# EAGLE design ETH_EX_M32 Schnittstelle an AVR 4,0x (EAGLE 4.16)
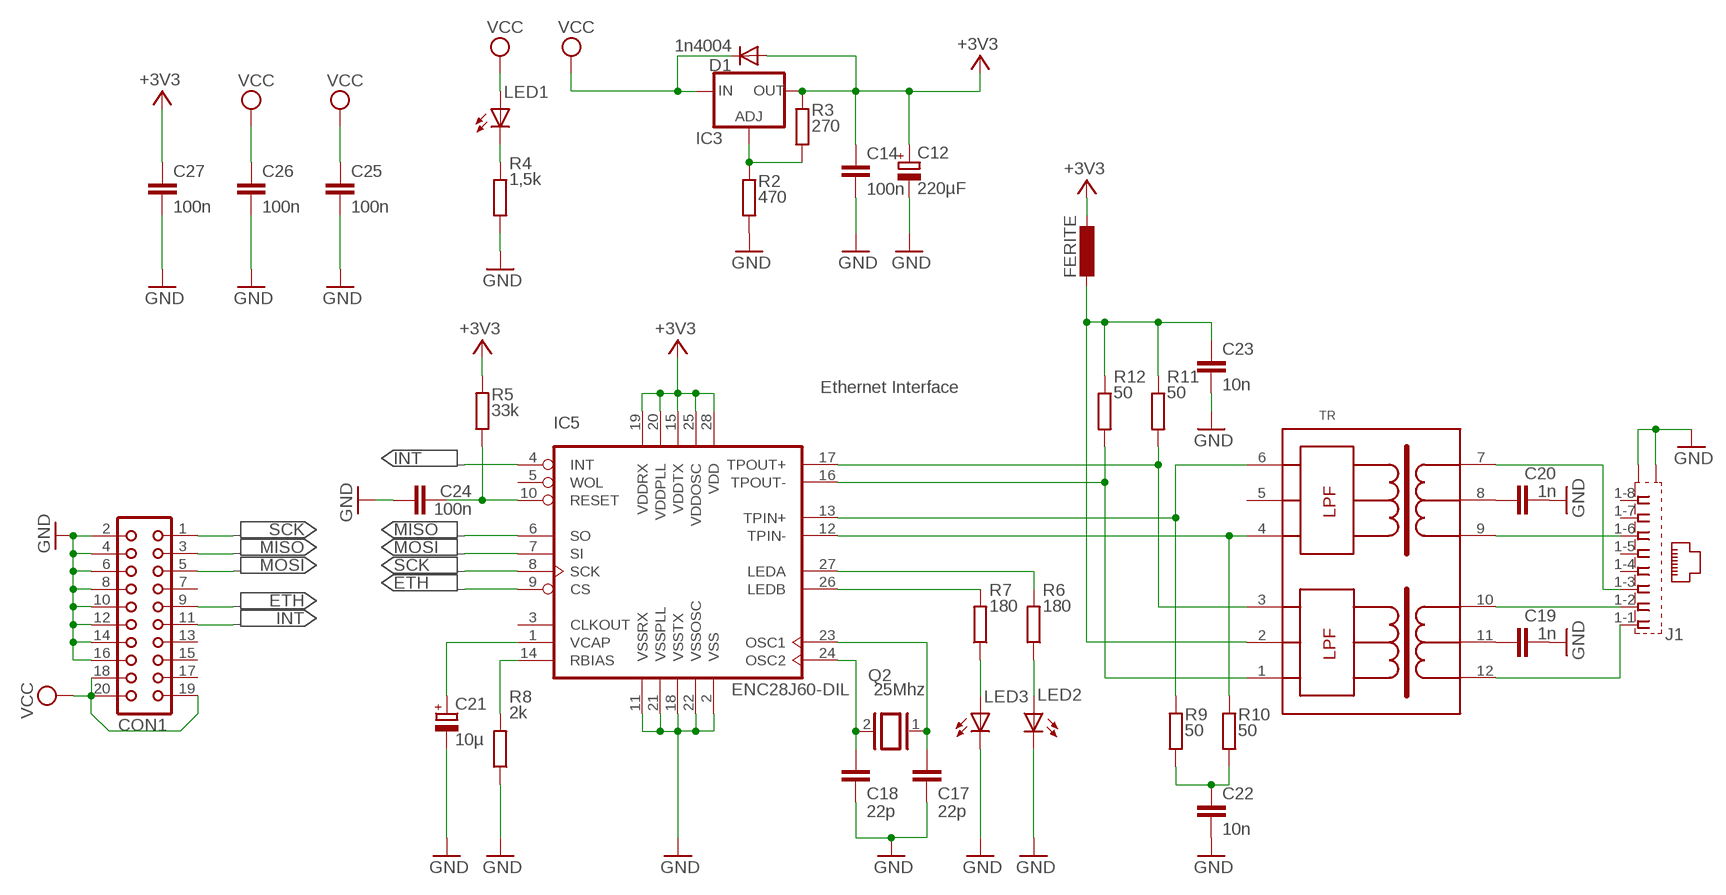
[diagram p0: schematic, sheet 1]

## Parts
C12  220µF  CPOL-EUE3.5-8  [E3,5-8]
C14  100n  C-EU025-024X044  [C025-024X044]
C17  22p  C-EU025-024X044  [C025-024X044]
C18  22p  C-EU025-024X044  [C025-024X044]
C19  1n  C-EU025-024X044  [C025-024X044]
C20  1n  C-EU025-024X044  [C025-024X044]
C21  10µ  CPOL-EUE2.5-5  [E2,5-5]
C22  10n  C-EU025-025X050  [C025-025X050]
C23  10n  C-EU025-025X050  [C025-025X050]
C24  100n  C-EU025-024X044  [C025-024X044]
C25  100n  C-EU025-025X050  [C025-025X050]
C26  100n  C-EU025-025X050  [C025-025X050]
C27  100n  C-EU025-025X050  [C025-025X050]
CON1  CON20  [CON20]
D1  1n4004  DIODE-D-7.5  [D-7.5]
FERITE  L-EU0204/5  [0204/5]
IC3  LM317TS  [317TS]
IC5  ENC28J60-DIL  [DIL28-3]
J1  557786-1  [557786-1]
LED1  LED3MM  [LED3MM]
LED2  LED3MM  [LED3MM]
LED3  LED3MM  [LED3MM]
Q2  25Mhz  XTAL/S  [QS]
R2  470  R-EU_0204/7  [0204/7]
R3  270  R-EU_0204/7  [0204/7]
R4  1,5k  R-EU_0204/7  [0204/7]
R5  33k  R-EU_0204/7  [0204/7]
R6  180  R-EU_0204/7  [0204/7]
R7  180  R-EU_0204/7  [0204/7]
R8  2k  R-EU_0204/7  [0204/7]
R9  50  R-EU_0204/7  [0204/7]
R10  50  R-EU_0204/7  [0204/7]
R11  50  R-EU_0204/7  [0204/7]
R12  50  R-EU_0204/7  [0204/7]
TR  20F001  [DIL16/12]

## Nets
+3V3: C12.+ C14.1 C27.1 D1.A FERITE.1 IC3.2(OUT) IC5.15(VDDTX) IC5.19(VDDRX) IC5.20(VDDPLL) IC5.25(VDDOSC) IC5.28(VDD) R3.2 R5.2
ETH: CON1.9 IC5.9(CS)
GND: C12.- C14.2 C17.1 C18.1 C19.2 C20.2 C21.- C22.2 C23.2 C24.1 C25.1 C26.2 C27.2 CON1.2 CON1.4 CON1.6 CON1.8 CON1.10 CON1.12 CON1.14 CON1.16 IC5.2(VSS) IC5.11(VSSRX) IC5.18(VSSTX) IC5.21(VSSPLL) IC5.22(VSSOSC) J1.G1(S2) J1.G2(S1) LED2.K(C) LED3.K(C) R2.1 R4.1 R8.1
INT: CON1.11 IC5.4(INT)
MISO: CON1.3 IC5.6(SO)
MOSI: CON1.5 IC5.7(SI)
N$4: LED1.K(C) R4.2
N$7: J1.1-1 TR.12
N$8: J1.1-2 TR.10
N$11: IC5.27(LEDA) R6.2
N$12: IC3.1(ADJ) R2.2 R3.1
N$13: J1.1-6 TR.9
N$14: IC5.26(LEDB) R7.2
N$15: J1.1-3 TR.7
N$16: C20.1 TR.8
N$17: C19.1 TR.11
N$18: LED3.A R7.1
N$19: LED2.A R6.1
N$20: C18.2 IC5.24(OSC2) Q2.2
N$21: C17.2 IC5.23(OSC1) Q2.1
N$22: IC5.12(TPIN-) R10.2 TR.4
N$23: IC5.13(TPIN+) R9.2 TR.6
N$24: IC5.16(TPOUT-) R12.2 TR.1
N$25: IC5.17(TPOUT+) R11.2 TR.3
N$26: IC5.14(RBIAS) R8.2
N$27: C21.+ IC5.1(VCAP)
N$29: C22.1 R9.1 R10.1
N$30: C24.2 IC5.10(RESET) R5.1
N$248: C23.1 FERITE.2 R11.1 R12.1 TR.2
SCK: CON1.1 IC5.8(SCK)
VCC: C25.2 C26.1 CON1.18 CON1.19 CON1.20 D1.C IC3.3(IN) LED1.A
Unconnected: CON1.7 CON1.13 CON1.15 CON1.17 IC5.3(CLKOUT) IC5.5(WOL) J1.1-4 J1.1-5 J1.1-7 J1.1-8 TR.5

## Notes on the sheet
- Ethernet Interface

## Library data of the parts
C12 C21 = rcl:CPOL-EU: POLARIZED CAPACITOR, European symbol
C14 C17-C20 C22-C27 = rcl:C-EU: CAPACITOR, European symbol
CON1 = con-harting:CON20: CONNECTOR
D1 = diode:DIODE-: DIODE
FERITE = rcl:L-EU: INDUCTOR, European symbol
IC3 = v-reg:LM317TS: VOLTAGE REGULATOR
IC5 = enc28j60centered:ENC28J60-*: Microchip 10Mbit Ethernet controller with SPI interface Improved SOIC28 layout (pads in 0.01 raster, pin1 slightly smaller). Pin 6 (SO) changed from Out (paralleling several Outs gives an error) to OC. Author: Profi from mikrocontroller.net - forum Date: 2006.0827
J1 = con-amp:557786-1: AMP connector
LED1-LED3 = led:LED: LED
Q2 = special:XTAL/S: CRYSTAL
R2-R12 = rcl:R-EU_: RESISTOR, European symbol
TR = Realtek:20F001

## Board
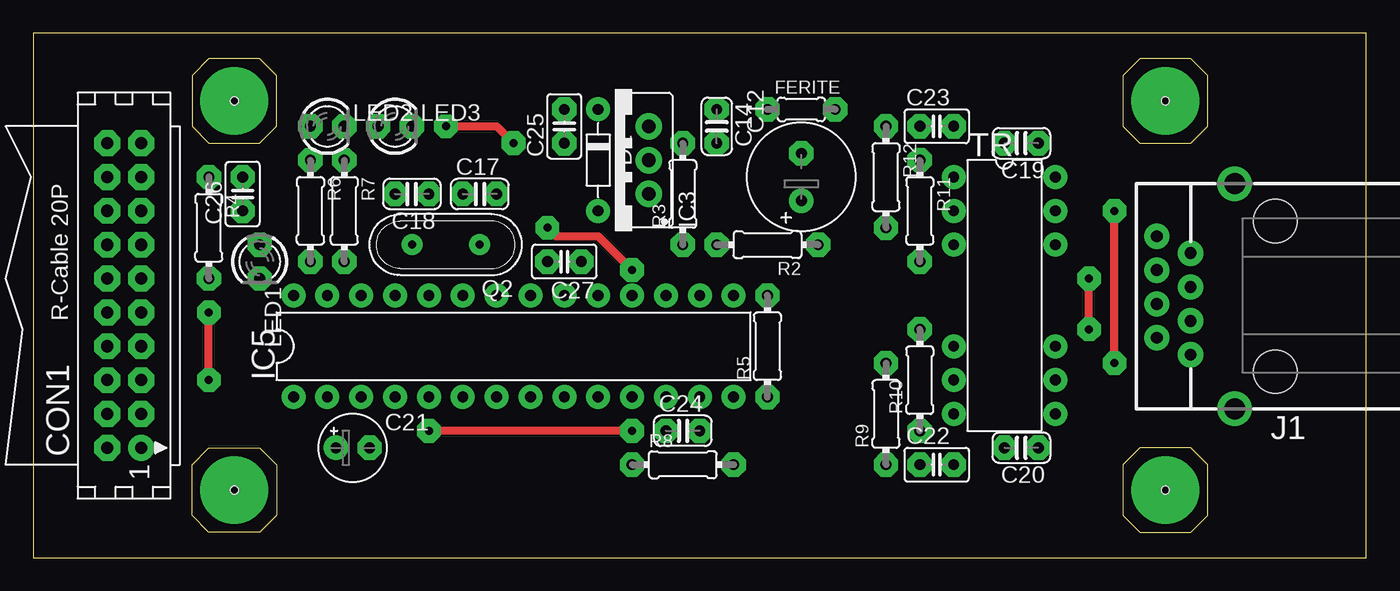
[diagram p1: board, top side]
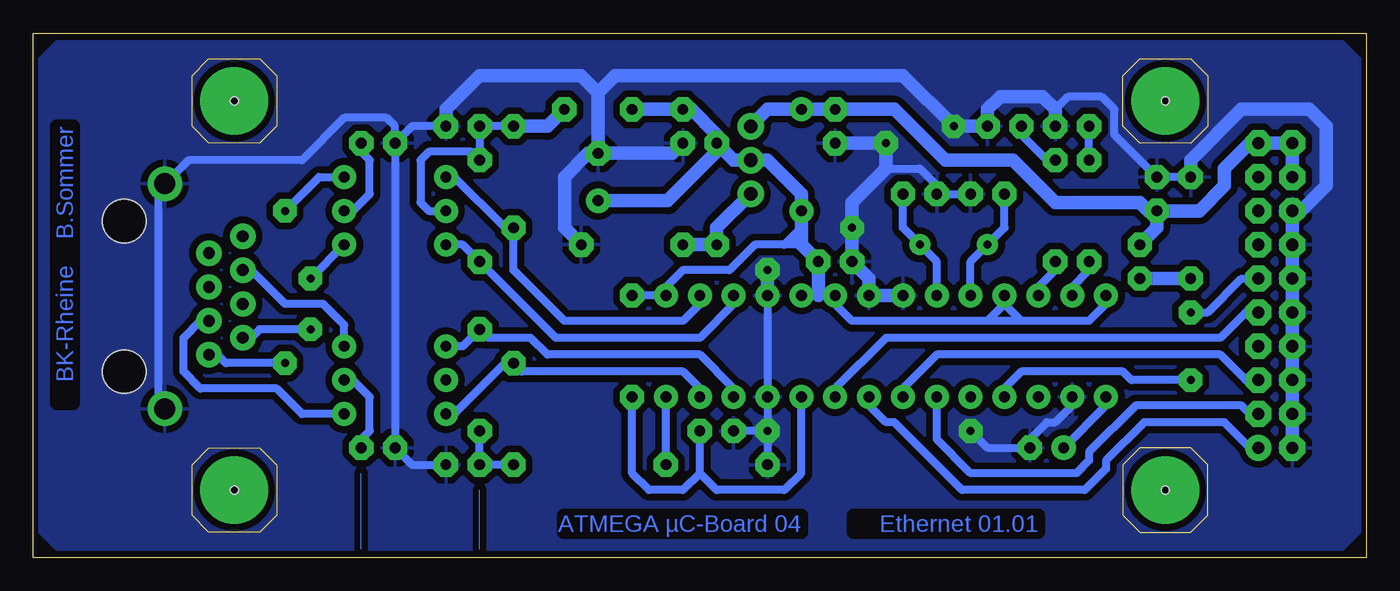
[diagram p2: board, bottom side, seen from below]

Size 100 x 39.36 mm. Coordinates in mm from the lower left corner, seen from the top.
Outline: 0,0 100,0 100,39.36 0,39.36 0,0
Outline: 16.98,37.46 13.17,37.46 11.9,36.19 11.9,32.38 13.17,31.11 16.98,31.11 18.25,32.38 18.25,36.19 16.98,37.46
Outline: 13.17,8.25 16.98,8.25 18.25,6.98 18.25,3.17 16.98,1.9 13.17,1.9 11.9,3.17 11.9,6.98 13.17,8.25
Outline: 83.02,1.9 86.83,1.9 88.1,3.17 88.1,6.98 86.83,8.25 83.02,8.25 81.75,6.98 81.75,3.17 83.02,1.9
Outline: 83.02,31.11 86.83,31.11 88.1,32.38 88.1,36.19 86.83,37.46 83.02,37.46 81.75,36.19 81.75,32.38 83.02,31.11
Copper layers (1*16): Top 0.035mm / dielectric 1.5mm / Bottom 0.035mm
Design rules "sommer_01": minimum track width 24mil, minimum drill 0.5mm, track to track 20mil, track to pad 24mil, pad to pad 24mil, via to via 24mil, smd to smd 8mil, copper to edge 0mil, drill to drill 8mil, minimum pad ring 20mil, minimum via ring 20mil, stop-mask expansion 4mil, vias tented up to drill 0mil, thermal gap 20mil
Holes 0.6 mm at 15.08,5.08 15.08,34.29 84.92,34.29 84.92,5.08

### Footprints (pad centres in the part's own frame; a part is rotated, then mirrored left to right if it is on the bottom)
E3,5-8 = drill 0.813 pad 1.6 round: + -1.778,0 | drill 0.813 pad 1.6 octagon: - 1.778,0
C025-024X044 = drill 0.813 octagon: 1 -1.27,0; 2 1.27,0
E2,5-5 = drill 0.813 pad 1.6 round: + -1.27,0 | drill 0.813 pad 1.6 octagon: - 1.27,0
C025-025X050 = drill 0.813 octagon: 1 -1.27,0; 2 1.27,0
CON20 = drill 0.914 round: 1 -11.43,-1.27 | drill 0.914 octagon: 2 -11.43,1.27; 3 -8.89,-1.27; 4 -8.89,1.27; 5 -6.35,-1.27; 6 -6.35,1.27; 7 -3.81,-1.27; 8 -3.81,1.27; 9 -1.27,-1.27; 10 -1.27,1.27; 11 1.27,-1.27; 12 1.27,1.27; 13 3.81,-1.27; 14 3.81,1.27; 15 6.35,-1.27; 16 6.35,1.27; 17 8.89,-1.27; 18 8.89,1.27; 19 11.43,-1.27; 20 11.43,1.27
D-7.5 = drill 0.813 long: A 3.81,0; C -3.81,0
0204/5 = drill 0.813 octagon: 1 -2.54,0; 2 2.54,0
317TS = drill 1.016 long: 1 -2.54,-2.54; 2 0,-2.54; 3 2.54,-2.54
DIL28-3 = drill 0.813 long: 1 -16.51,-3.81; 2 -13.97,-3.81; 3 -11.43,-3.81; 4 -8.89,-3.81; 5 -6.35,-3.81; 6 -3.81,-3.81; 7 -1.27,-3.81; 8 1.27,-3.81; 9 3.81,-3.81; 10 6.35,-3.81; 11 8.89,-3.81; 12 11.43,-3.81; 13 13.97,-3.81; 14 16.51,-3.81; 15 16.51,3.81; 16 13.97,3.81; 17 11.43,3.81; 18 8.89,3.81; 19 6.35,3.81; 20 3.81,3.81; 21 1.27,3.81; 22 -1.27,3.81; 23 -3.81,3.81; 24 -6.35,3.81; 25 -8.89,3.81; 26 -11.43,3.81; 27 -13.97,3.81; 28 -16.51,3.81
557786-1 = drill 0.889 round: 1-1 -4.445,6.35; 1-2 -3.175,8.89; 1-3 -1.905,6.35; 1-4 -0.635,8.89; 1-5 0.635,6.35; 1-6 1.905,8.89; 1-7 3.175,6.35; 1-8 4.445,8.89 | drill 1.575 pad 2.184 round: G1 -8.509,3.048; G2 8.382,3.048 | hole 3.251: -5.715,0; 5.588,0
LED3MM = drill 0.813 octagon: A -1.27,0; K 1.27,0
QS = drill 0.61 long: 1 -2.54,0; 2 2.54,0
0204/7 = drill 0.813 octagon: 1 -3.81,0; 2 3.81,0
DIL16/12 = drill 0.813 long: 1 -8.89,-3.81; 2 -6.35,-3.81; 3 -3.81,-3.81; 4 3.81,-3.81; 5 6.35,-3.81; 6 8.89,-3.81; 7 8.89,3.81; 8 6.35,3.81; 9 3.81,3.81; 10 -3.81,3.81; 11 -6.35,3.81; 12 -8.89,3.81

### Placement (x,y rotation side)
C12  57.62,28.57 90 top
C14  51.27,32.38 270 top
C17  33.49,27.3 0 top
C18  28.41,27.3 180 top
C19  74.13,31.11 180 top
C20  74.13,8.25 180 top
C21  23.96,8.25 0 top
C22  67.78,6.98 0 top
C23  67.78,32.38 0 top
C24  48.73,9.52 0 top
C25  39.84,32.38 90 top
C26  15.71,27.3 90 top
C27  39.84,22.22 180 top
CON1  6.82,19.68 90 top
D1  42.38,29.84 270 top
FERITE  57.62,33.65 0 top
IC3  43.65,29.84 90 top
IC5  36.03,15.87 0 top
J1  93.18,19.68 90 top
LED1  16.98,22.22 270 top
LED2  22.06,32.38 0 top
LED3  27.14,32.38 0 top
Q2  30.95,23.49 180 top
R2  55.08,23.49 180 top
R3  48.73,27.3 90 top
R4  13.17,24.76 270 top
R5  55.08,15.87 90 top
R6  20.79,26.03 270 top
R7  23.33,26.03 270 top
R8  48.73,6.98 0 top
R9  63.97,10.79 90 top
R10  66.51,13.33 90 top
R11  66.51,26.03 270 top
R12  63.97,28.57 270 top
TR  72.86,19.68 270 top

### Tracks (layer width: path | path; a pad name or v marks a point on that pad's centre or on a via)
+3V3
  Bottom 0.61: R5.2 IC5.15 52.54,20.31 51.27,21.58 47.78,21.58 45.87,23.49 43.65,23.49 | IC5.19 41.11,19.68 IC5.20 39.84,19.04 38.57,17.77 28.41,17.77 | IC5.28 19.52,19.04 20.79,17.77 25.87,17.77 | 25.87,17.77 27.14,19.04 | 27.14,19.04 IC5.25 | 27.14,19.04 28.41,17.77 | 25.87,17.77 28.41,17.77 | 42.38,23.49 43.65,23.49 | 42.38,24.76 43.65,23.49
  Bottom 1.016: R3.2 47.46,29.84 IC3.2 44.92,29.84 42.38,27.3 D1.A 42.38,24.76 42.38,23.49 C27.1 41.11,19.68 | C12.+ 52.41,26.79 48.73,30.47 R3.2 | R3.2 48.73,31.74 50.63,33.65 C14.1 FERITE.1
ETH
  Bottom 0.61: CON1.9 9.04,18.41 10.95,16.5 36.03,16.5 39.84,12.7 IC5.9
GND  (via drill 0.6 pad 1.78)
  Top 0.61: v30.95,32.38 34.76,32.38 v36.03,31.11 | v38.57,24.76 39.2,24.12 42.38,24.12 v44.92,21.58 | v44.92,9.52 v29.68,9.52
  Bottom 0.61: J1.G1 90.13,11.55 90.64,12.06 90.64,27.3 90.13,27.81 J1.G2 88.35,29.84 79.84,29.84 76.67,33.02 73.5,33.02 72.86,32.38 C19.2 | IC5.18 IC5.11 v44.92,9.52 | v44.92,9.52 R8.1 | C23.2 71.59,32.38 C19.2 | C22.2 71.59,6.98 C20.2 C19.2 | C18.1 C17.1 32.22,27.93 33.49,29.2 36.03,29.2 | R4.1 C26.2 18.88,31.74 18.88,33.65 19.84,34.6 22.38,34.6 23.33,33.65 | v29.68,9.52 28.41,8.25 C21.- 25.23,8.89 23.96,10.16 23.33,10.16 22.06,11.43 IC5.2 | v44.92,9.52 C24.1
  Bottom 1.016: 57.62,34.92 C12.- | 57.62,34.92 58.89,36.19 66.51,36.19 69.05,33.65 C23.2 | CON1.2 CON1.4 CON1.6 CON1.8 CON1.10 CON1.12 CON1.14 CON1.16 4.92,26.03 3.01,27.93 3.01,32.38 4.28,33.65 9.36,33.65 13.17,29.84 R4.1 | 57.62,34.92 56.35,36.19 34.76,36.19 v30.95,32.38 LED3.K 28.41,33.65 27.46,34.6 24.28,34.6 23.33,33.65 LED2.K | C25.1 v36.03,31.11 36.03,29.2 38.57,26.66 v38.57,24.76 C27.2 37.3,20.95 IC5.21 IC5.22 | v44.92,21.58 IC5.18 | C12.- 52.03,30.35 C14.2 | C12.- 58.38,30.35 60.16,28.57 60.16,24.76 R2.1
  pour Bottom: 0.47,37.46 1.74,38.73 98.26,38.73 99.53,37.46 99.53,1.9 98.26,0.63 1.74,0.63 0.47,1.9
INT  (via drill 0.6 pad 1.78)
  Top 0.61: v13.17,13.33 v13.17,18.41
  Bottom 0.61: v13.17,18.41 11.9,18.41 9.36,20.95 CON1.11 | v13.17,13.33 17.61,13.33 18.25,13.97 25.87,13.97 27.14,12.7 IC5.4
MISO
  Bottom 0.61: CON1.3 8.73,10.79 9.36,11.43 17.3,11.43 20.79,7.93 20.79,7.3 21.74,6.34 29.68,6.34 32.22,8.89 IC5.6
MOSI
  Bottom 0.61: IC5.7 34.76,12.7 32.22,15.24 10.95,15.24 9.04,13.33 CON1.5
N$1  (via drill 0.6 pad 5.08)
  other vias: 15.08,34.29
N$2  (via drill 0.6 pad 5.08)
  other vias: 15.08,5.08
N$3  (via drill 0.6 pad 5.08)
  other vias: 84.92,5.08
N$4
  Bottom 1.016: R4.2 LED1.K
N$5  (via drill 0.6 pad 5.08)
  other vias: 84.92,34.29
N$6
  Bottom 0: 66.51,0.63 66.51,5.08
N$7  (via drill 0.6 pad 1.78)
  Top 0.61: v81.11,14.6 v81.11,26.03
  Bottom 0.61: J1.1-1 86.19,15.24 85.56,14.6 v81.11,14.6 | v81.11,26.03 78.58,28.57 TR.12
N$8  (via drill 0.6 pad 1.78)
  Top 0.61: v79.21,17.14 v79.21,20.95
  Bottom 0.61: v79.21,20.95 TR.10 | v79.21,17.14 83.02,17.14 83.66,16.5 J1.1-2
N$9
  Bottom 0: 75.4,0.63 75.4,6.34
N$10
  pour Bottom: 1.74,37.46 98.26,37.46 98.26,1.9 1.74,1.9
N$11
  Bottom 0.61: R6.2 20.79,21.58 22.06,20.31 IC5.27
N$12
  Bottom 1.016: IC3.1 48.73,24.76 R3.1 R2.2
N$13
  Bottom 0.61: TR.9 76.67,17.46 78.26,19.04 81.11,19.04 83.66,21.58 J1.1-6
N$14
  Bottom 0.61: R7.2 23.33,21.58 24.6,20.31 IC5.26
N$15
  Bottom 0.61: TR.7 79.84,10.79 81.75,12.7 87.47,12.7 88.73,13.97 88.73,16.5 87.47,17.77 J1.1-3
N$16
  Bottom 0.61: TR.8 76.03,13.33 74.77,12.06 74.77,9.52 75.4,8.89 C20.1
N$17
  Bottom 0.61: TR.11 76.03,26.03 74.77,27.3 74.77,29.84 75.4,30.47 C19.1
N$18
  Bottom 0.61: R7.1 23.96,29.84 25.87,31.74 LED3.A
N$19
  Bottom 0.61: R6.1 LED2.A
N$20
  Bottom 0.61: IC5.24 29.68,22.22 Q2.2 27.14,24.76 C18.2
N$21
  Bottom 0.61: IC5.23 32.22,22.22 Q2.1 34.76,24.76 C17.2
N$22
  Bottom 0.61: IC5.12 47.46,12.7 50,15.24 61.43,15.24 62.7,16.5 65.88,16.5 R10.2 67.78,15.87 TR.4
N$23
  Bottom 0.61: IC5.13 50,12.7 51.27,13.97 63.34,13.97 R9.2 64.61,14.6 68.41,10.79 TR.6
N$24
  Bottom 0.61: IC5.16 50,19.04 51.27,17.77 60.16,17.77 63.97,21.58 R12.2 64.61,24.76 68.41,28.57 TR.1
N$25
  Bottom 0.61: IC5.17 47.46,19.04 50,16.5 60.8,16.5 R11.2 67.78,23.49 TR.3
N$26
  Bottom 0.61: R8.2 IC5.14
N$27
  Bottom 0.61: IC5.1 19.52,11.43 C21.+
N$29
  Bottom 0.61: R10.1 C22.1 R9.1
N$30
  Bottom 0.61: R5.1 55.08,6.34 53.81,5.08 51.27,5.08 50,6.34 | IC5.10 42.38,6.34 43.65,5.08 48.73,5.08 50,6.34 | 50,6.34 C24.2
N$248
  Bottom 0.61: TR.2 70.32,26.03 70.95,26.66 70.95,29.84 70.32,30.47 67.14,30.47 R11.1 C23.1 R12.1
  Bottom 1.016: FERITE.2 61.43,32.38 R12.1
SCK
  Bottom 0.61: CON1.1 8.73,8.25 10.63,10.16 16.66,10.16 19.52,7.3 19.52,6.66 21.11,5.08 30.31,5.08 35.39,10.16 36.03,10.16 37.3,11.43 IC5.8
VCC
  Bottom 1.016: IC3.3 44.92,33.65 D1.C C25.2 35.39,33.65 31.58,29.84 26.5,29.84 23.33,26.66 16.98,26.66 16.34,26.03 C26.1 | CON1.18 CON1.20 CON1.19 8.73,31.11 10.63,29.2 10.63,27.93 12.54,26.03 C26.1 | LED1.A 15.71,24.76 C26.1

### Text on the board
Bottom: BK-Rheine B.Sommer | Ethernet 01.01 | ATMEGA µC-Board 04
